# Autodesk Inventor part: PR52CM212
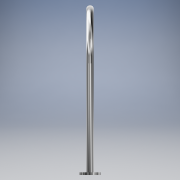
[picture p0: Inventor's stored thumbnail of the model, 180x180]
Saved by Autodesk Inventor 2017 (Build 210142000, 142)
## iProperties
Created: 2021-04
Part Number: PR52CM212
Material: Generico
Document SubType Name: Modeling
Designer: PIZZERA
Density: 1 g/cm^3
Appearance: Default
Author: PIZZERA
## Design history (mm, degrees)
feature "Base3"
node "Solido1"
node "Solido4"
